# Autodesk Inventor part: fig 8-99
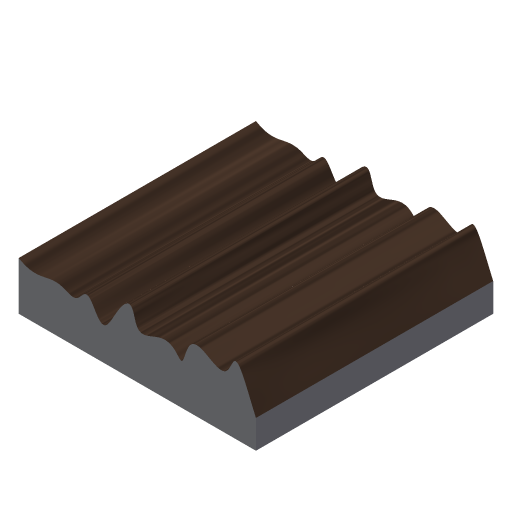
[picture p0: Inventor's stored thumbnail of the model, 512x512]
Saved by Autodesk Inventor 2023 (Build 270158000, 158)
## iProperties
Part Number: fig 8-99
Document SubType Name: Modeling
Created: 2002-12
Designer: deepak
Density: 1 g/cm^3
Material: Generic
Appearance: Default
Control State: 0
Master: False
Checked Out: False
Shininess: 64.0
Length Units: 11269
Angle Units: 11279
Time Units: 11290
Mass Units: 11283
Length Display Precision: 3
Angle Display Precision: 2
Compacted: True
Density: 0.0
Volumn: 0.0
Area: 0.0
PropertySet Name: Model Information
Author: deepak
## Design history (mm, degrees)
sketch "Sketch1"
  geometry: L1 (-32.188, 30.089)-(27.812, 30.089); L2 (27.812, 30.089)-(27.812, -29.911); L3 (27.812, -29.911)-(-32.188, -29.911); L4 (-32.188, -29.911)-(-32.188, 30.089)
  constraints: 8 end point, 2 parallel, 1 horizontal, 1 perpendicular
  dimensions: "d0" = 60 distance of L1.start L1.end; "d1" = 60 distance of L3.end L1.start
extrude "Extrusion1" new body sketch "Sketch1" stored distance "d2" = 20; taper "d3" = 0 deg
sketch "Sketch2"
  geometry: 17 further points
  constraints: 17 other
extrude_surface "ExtrusionSrf1" sketch "Sketch2" dims "d4" = 70, "d5" = 0
split "Split1"
body "Solid1"
body "Srf1"
